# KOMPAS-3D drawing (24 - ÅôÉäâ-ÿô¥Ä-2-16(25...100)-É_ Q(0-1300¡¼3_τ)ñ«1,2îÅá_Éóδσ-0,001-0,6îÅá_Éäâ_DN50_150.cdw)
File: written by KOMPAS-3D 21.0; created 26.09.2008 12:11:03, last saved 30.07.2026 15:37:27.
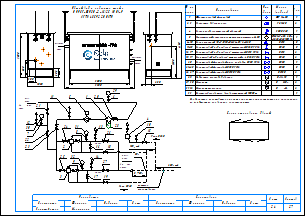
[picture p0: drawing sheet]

Sheets 1-2: A3, landscape

Document properties: Наименование: Макро:21; Автор: RaskoAdmin; Форматы листов документа: 2xA3; Полное имя файла: \\ur38nt01\Departments\КТО\КБ ПУРДГ\Заявки\Прайс-лист на типовые шкафы ГРПШ\ПУРДГ_стандарт_30_04_2026\ПУРДГ с РДГ(Н, В)\ПУРДГ-ШУЭО-2-16(25...100)-Р_ Q(0-1300нм3_ч)до1,2МПа_Рвых-0,001-0,6МПа_РДГ_DN50_150.cdw

Title block, sheet 1: Наименование: Пункт учета газа / ПУГ-Ш-400-Р / ЛГТИ.485922.001ТУ; designation: ЛГТИ.03.4411141; sheet number: 1; Количество листов документа: 2; organisation: ООО "ЭЛЬСТЕР Газэлектроника"; Форматы листов документа: A3; stored path: C:\Рабочие документы\Компас\ПУГ\Схема.cdw; Разработал: Устинов; Проверил: Кошкин; Утвердил: Кошкин
Title block, sheet 2: sheet number: 2; stored path: D:\Рабочие документы\Заявки\ПУРДГ\ПУРДГ-ШУЭО-2-100-Р 4411220.cdw; designation, second copy: ЛГТИ.03.4411141-

Views: Вид 1, Вид 2
Referenced files: wcvoit.frw
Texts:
  Normal
  № на
  схеме
  Усл.
  обозн.
  Марка
  (модель)
  Кол.
  Фильтр газовый фланцевый
  ФГ 16-50
  Регулятор давления газа
  РДГ-50
  Клапан предохранительный сбросной
  КПС DN20
  Измерительный комплекс с ротационным счетчиком Ду50
  СГ-ЭК-Р-(0,2...2,0)-
  Кран кнопочный VE-РАСКО-НЗ-1,6-G1/2-М20
  DN15
  Кран шаровой "под приварку" штуцерный DN20 PN16
  DN20
  Кран шаровой "под приварку" штуцерный DN15 PN16
  Кран шаровой "под приварку" штуцерный п/п DN20 PN16
  Кран шаровой фланцевый с мех. приводом DN50 PN16
  Кран шаровой фланцевый DN50 PN16
  Кран шаровой фланцевый DN150 PN16
  DN50
  DN150
  Индикатор перепада давления
  Манометр
  Манометр-напоромер
  Электрообогреватель взрывозащищенный 1000Вт
  Delta 15
  0...     МПа
  0...     кПа
  Общий вид и габариты шкафа
  ПУРДГ-ШУЭО-2-16(25...100)-Р
  Выход газа
  Вход газа
  logo-rasko-ge.png
  DN 1
  местное
  сопротивление
  Римп DN20
  Выход
  газа
  Р=     кПа
  Вход
  Р=       МПа
  PDI
  Схема открывания дверей
  Предприятие изготовитель может заменять комплектующие на аналогичные,
  не ухудшающие заявленных характеристик.
  Должность
  Конструктор
  Фамилия
  Подпись
  Дата
  Согласовано
  Максимкин
  Лист
  Листов
  POLYLINE_STYLE_0.18_RGB_0_0_0
  POLYLINE_STYLE_0.50_RGB_0_0_0
  POLYLINE_STYLE_0.34_RGB_0_0_0
  PHANTOM_RGB_0_0_0_SC_1_THICK_0.18
  K5LT_THIN_RGB_0_0_0_THICK_0.18
  K5LT32769_RGB_0_0_0_THICK_0.18
  K5LT12_RGB_0_0_0_SC_1_THICK_0.18
  K5LT_DASHED_RGB_0_0_0_SC_1_THICK_0.18
  ACISOTGL_RGB_0_0_0_SC_0.8_THICK_0.25
  CONTINUOUS_RGB_0_127_31_THICK_0.3
  CONTINUOUS_RGB_0_0_255_THICK_0.35
  CONTINUOUS_RGB_255_0_0_THICK_0.35
  POLYLINE_STYLE_0.25_RGB_0_0_0
  CONTINUOUS_RGB_0_0_0_THICK_0.5
  POLYLINE_STYLE_0.35_RGB_0_0_255
  CONTINUOUS_RGB_0_0_0_THICK_0.4
  CONTINUOUS_RGB_0_0_0_THICK_0.35
  НЕВИДИМАЯ_RGB_0_0_0_SC_0.3_THICK_0.25
  СONTINUOUS_RGB_0_0_0_THICK_0.25
  ОСЕВАЯ2_RGB_248_153_30_SC_0.3_THICK_0.25
  Без оформления
Dimensions and other numbers on the sheet: 1; 2, 3; 2; 4; 5; 6-10; 11-15; 16, 17; 18, 19; 20; 21-25; 26, 27; 28; 29, 30; 31, 32; 33; 1500; 250; 300; 1050; 550; 305; 3000; 4130; 2000; 3300; 5,,,7DN 1; 7; 30; 12; 21; 22; 23; 11; 6; 29; 24; 31; 8; 13; 26; 18; 10; 15; 25; 32; 9; 3; 14; 27; 19; 16; 17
